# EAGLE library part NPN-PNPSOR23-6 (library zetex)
Dual NPN PNP TRANSISTOR
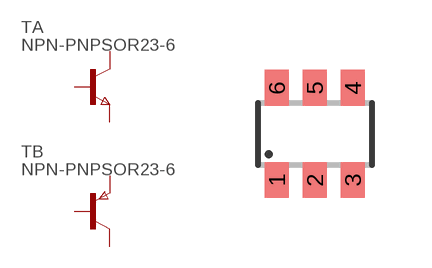
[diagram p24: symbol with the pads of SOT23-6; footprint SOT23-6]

Designator prefix T; gates A=NPN B=PNP

## NPN-PNPSOR23-6 (OC_FARNELL: unknown; OC_NEWARK: unknown)  [SOT23-6]
1  A:C  pas
2  A:B  pas
3  B:C  pas
4  B:E  pas
5  B:B  pas
6  A:E  pas

## Footprint SOT23-6 (pad centres in mm)
Small Outline Transistor 6 lead
smd 0.6 x 0.9: 1 -0.95,-1.15; 2 0,-1.15; 3 0.95,-1.15; 4 0.95,1.15; 5 0,1.15; 6 -0.95,1.15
